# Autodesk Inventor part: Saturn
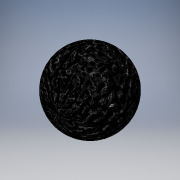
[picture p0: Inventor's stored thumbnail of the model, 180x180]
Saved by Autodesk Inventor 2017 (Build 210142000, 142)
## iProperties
Created: 2016-07
Part Number: Saturn
Material: Generic
Document SubType Name: Modeling
Designer: Stan
Density: 1 g/cm^3
Appearance: Glossy - Black
Author: Stan
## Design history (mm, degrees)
sketch "Sketch1"
  geometry: L1 (0, 22.225)-(0, -15.647); L2 (0, -15.647)-(-1.587, -15.647); L3 (-3.175, -21.997)-(-1.587, -21.997); L4 (-1.587, -15.647)-(-1.587, -21.997); A1 r 22.225 centre (0, 0) between (0, 22.225) and (-3.175, -21.997); 1 further point
  constraints: 8 end point, 2 point on circle, 1 centre point, 1 coincident, 1 horizontal, 1 perpendicular, 1 vertical
  dimensions: "d0" = 44.45 diameter of A1; "d2" = 0 distance from line of point (0, 0) L1; "d4" = 0 deg angle of L1 L4; "d5" = 3.175 distance from line of L1 L3.start; "d6" = 6.35 distance of L2.end L3.end; "d7" = 1.5875 distance from line of point (0, 0) L4
revolve "Revolution1" sketch "Sketch1" stored, may be unused: angle "d8" = 90 deg
body "Solid1"
